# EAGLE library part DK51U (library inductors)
FILTER
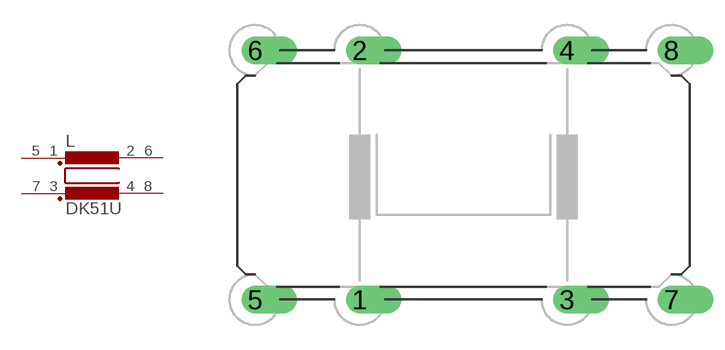
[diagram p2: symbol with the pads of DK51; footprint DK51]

Designator prefix L

## DK51U  [DK51]
1  1  pas
2  2  pas
3  3  pas
4  4  pas
5  5  pas
6  6  pas
7  7  pas
8  8  pas

## Footprint DK51 (pad centres in mm)
FILTER manufacturer Vogt
drill 1.118 offset: 1 -6.223,-7.493; 2 -6.223,7.493; 3 6.223,-7.493; 4 6.223,7.493; 5 -12.497,-7.493; 6 -12.497,7.493; 7 12.497,-7.493; 8 12.497,7.493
